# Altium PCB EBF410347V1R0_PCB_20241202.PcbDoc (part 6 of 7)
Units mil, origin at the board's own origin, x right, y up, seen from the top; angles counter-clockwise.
Board outline 5098.43 x 3464.57 mil, 6 copper layers (TOP, GND02, ART03, ART04, PWR05, BOTTOM), stack 47.2 mil thick; 566 components, 452 nets, 1905 pads, 1432 vias.
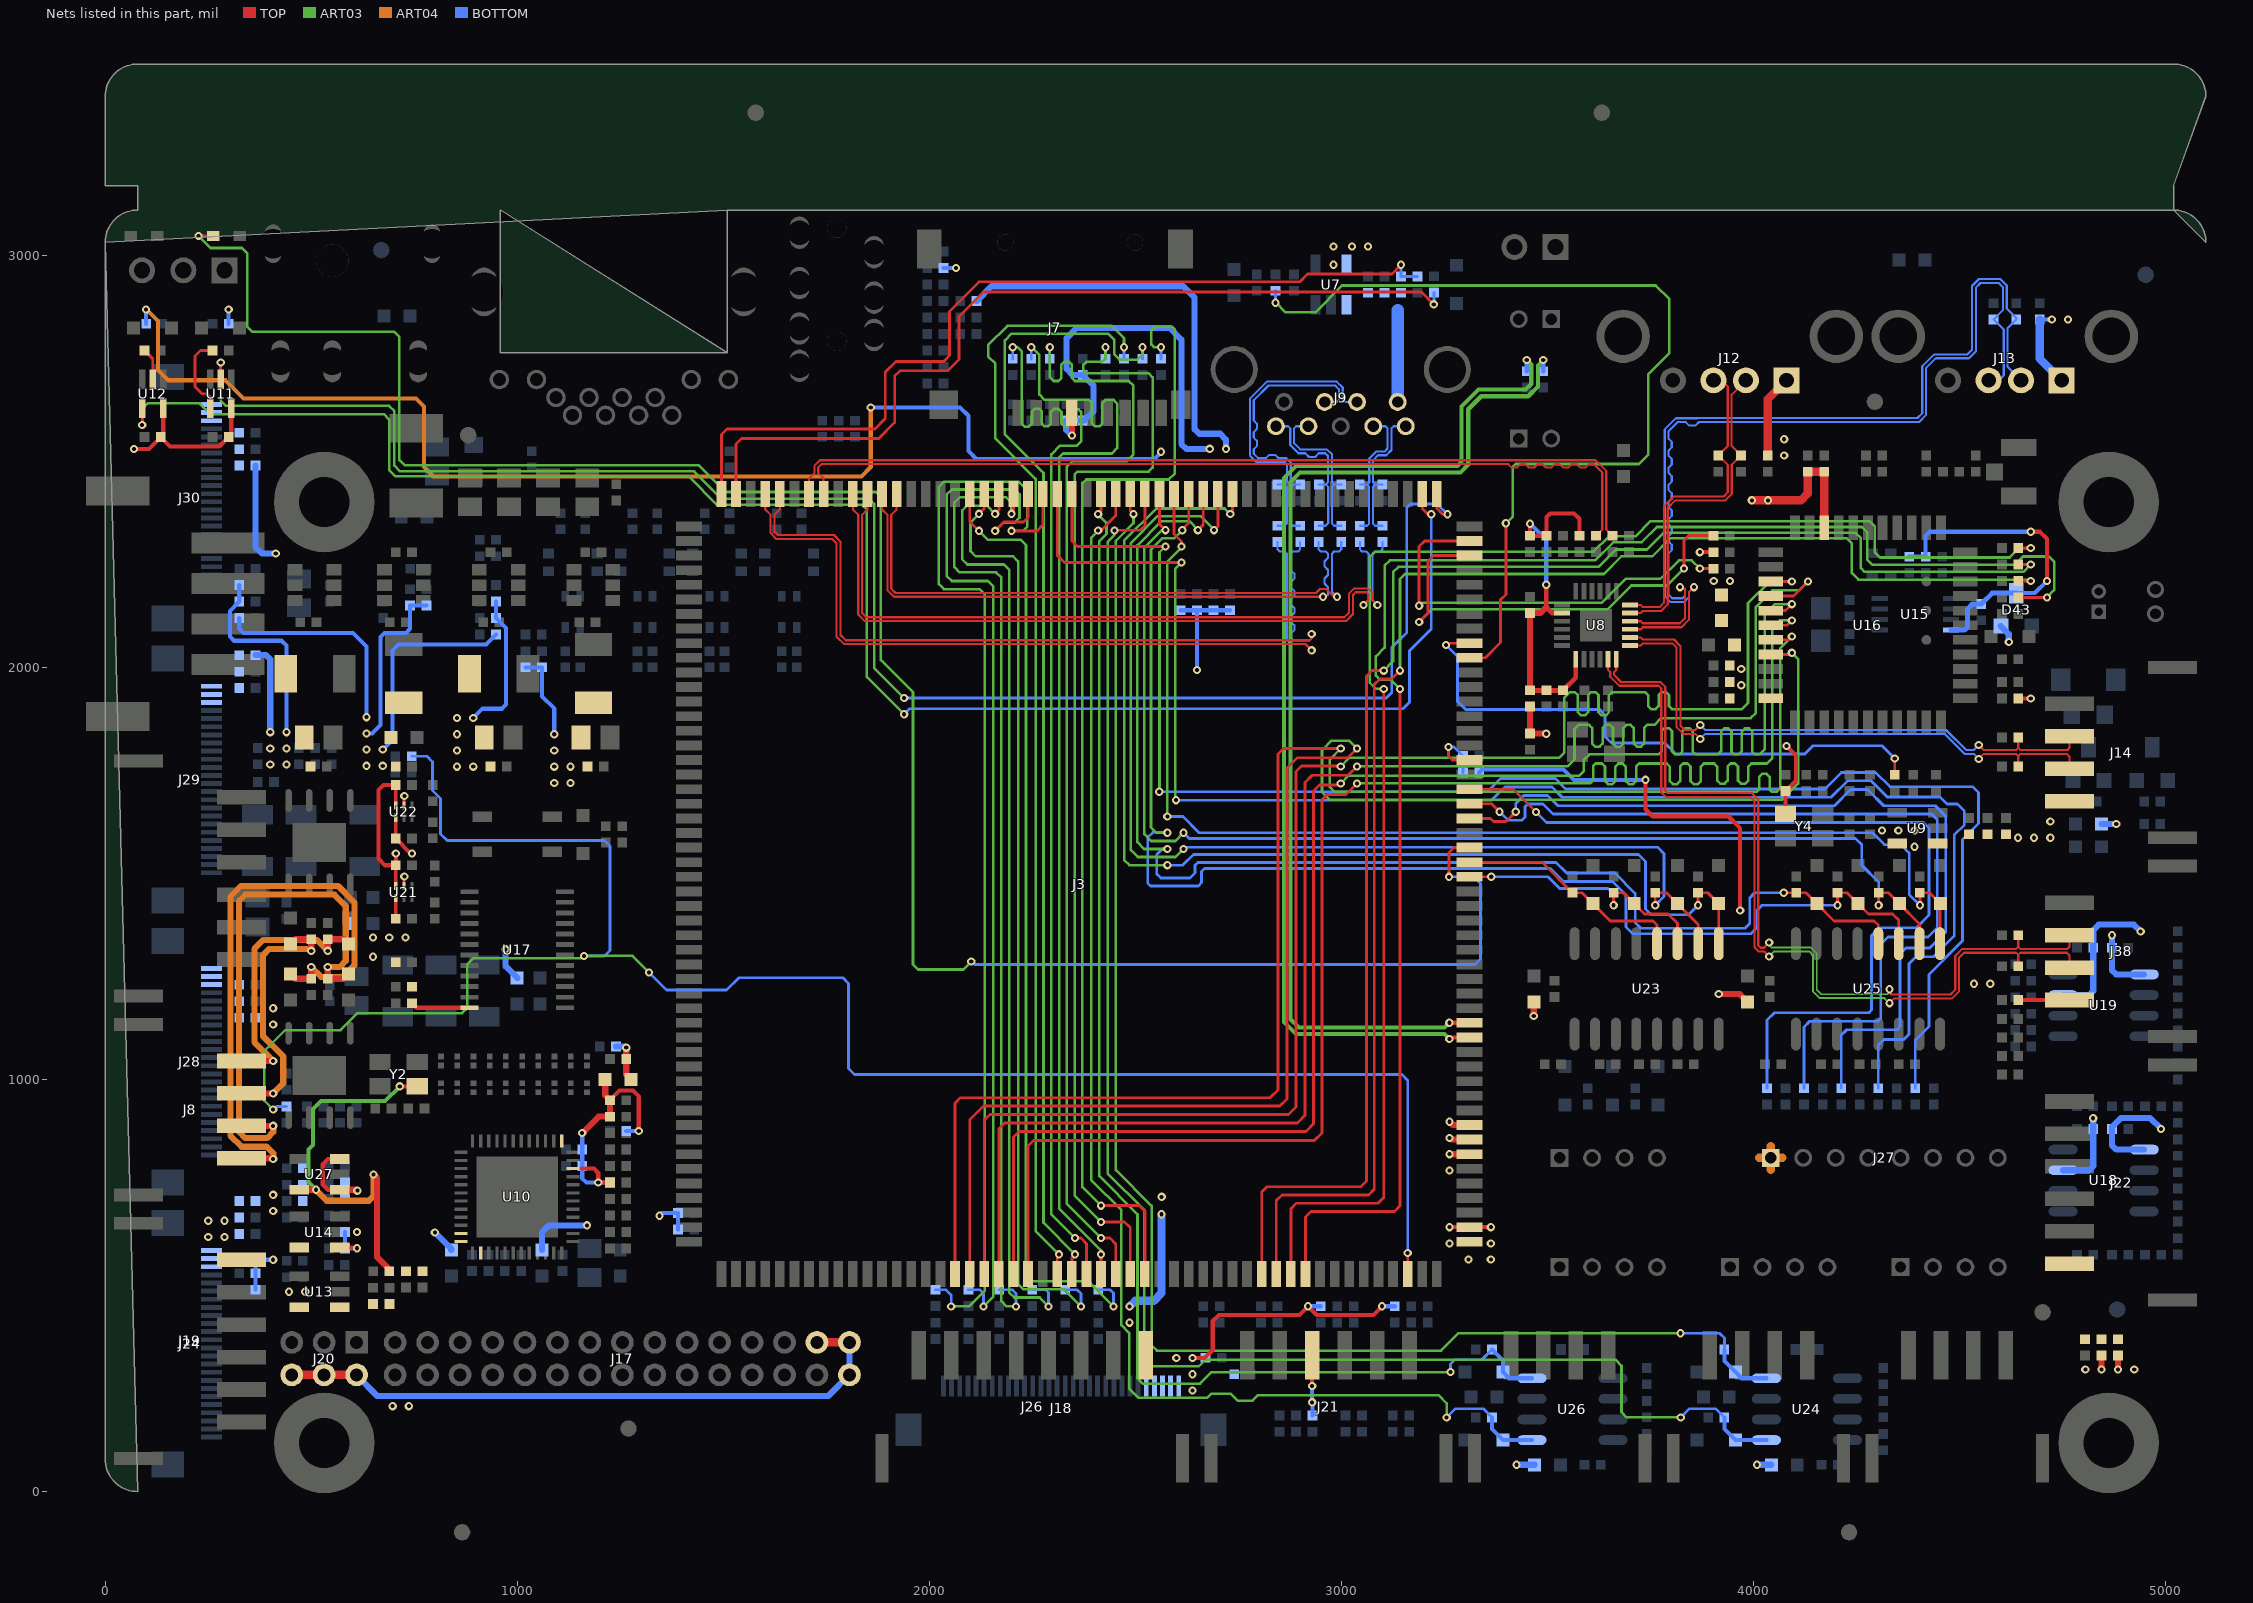
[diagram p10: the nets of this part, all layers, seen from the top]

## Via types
v1: diameter 20, hole 10, TOP to BOTTOM, 1432 vias

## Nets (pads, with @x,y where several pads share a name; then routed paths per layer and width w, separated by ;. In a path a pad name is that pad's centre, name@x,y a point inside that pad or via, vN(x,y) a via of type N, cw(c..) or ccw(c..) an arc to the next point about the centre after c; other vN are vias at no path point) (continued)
SARADC0_IN3: J3.34 R171.2 R173.1 | length 161
  TOP w6.8: v1(3260,1807.05) 3260,1785 3269.45,1775.55 J3.34@3310.59,1775.55
  BOTTOM w6.8: v1(3260,1807.05) 3273.27,1807.05 R173.1@3295.32,1785 R171.2@3295.32,1745
SARADC0_IN5: J3.32 R145.2 | length 2135.4
  TOP w6.8: J3.32@3310.59,1704.68 3416.99,1704.68 v1(3472.26,1649.41)
  BOTTOM w6.8: v1(3472.26,1649.41) 3497.9,1623.77 4412.51,1623.77 4426.11,1610.17 4426.11,1399 4395.34,1368.23 4306.23,1368.23 4287,1349 4287,1168.8 4280.2,1162 4051,1162 4033.11,1144.11 R145.2@4033.11,978.68
SARADC0_IN6: J3.31 R146.2 | length 2139
  TOP w6.8: J3.31@3310.59,1669.25 3364.62,1669.25 v1(3383.99,1649.88)
  BOTTOM w6.8: v1(3383.99,1649.88) 3404.39,1629.48 3438.79,1629.48 3446.11,1636.8 3446.11,1662.2 3452.91,1669 3489.11,1669 3513.94,1644.17 4432.91,1644.17 4446.51,1630.57 4446.51,1369 4423.51,1346 4327,1346 4309,1328 4309,1148.4 4302.2,1141.6 4136.71,1141.6 4123,1127.89 4123,978.79 R146.2@4123.11,978.68
SARADC0_IN7: J3.30 R147.2 | length 2122.7
  TOP w6.8: J3.30@3310.59,1633.82 3362.18,1633.82 3370,1626 3399.48,1626 v1(3423.36,1649.88)
  BOTTOM w6.8: v1(3423.36,1649.88) 3423.36,1670.25 3442.71,1689.6 3500.4,1689.6 3525.43,1664.57 4196.57,1664.57 4236,1704 4277,1704 4316.43,1664.57 4441.36,1664.57 4466.91,1639.02 4466.91,1622.12 4466.91,1357.91 4428,1319 4370,1319 4356,1305 4356,1127.8 4349.2,1121 4226.71,1121 4213.11,1107.4 R147.2@4213.11,978.68
SARADC1_IN0: J3.83 R139.2 | length 2317.3
  TOP w6.8: J3.83@2097.99,2421.22 2097.99,2354.19 v1(2120.55,2331.63)
  ART03 w6.3: v1(2120.55,2331.63) 2141.77,2310.41 2221.59,2310.41 2234.65,2297.35 2234.65,522.6 2247.25,510 2386.22,510 v1(2446.85,449.37)
  BOTTOM w6.8: R139.2@2410,489.68 2439.32,489.68 2446.85,482.15 v1(2446.85,449.37)
SARADC1_IN1: J3.82 R140.2 | length 2280.4
  TOP w6.8: v1(2120.55,2373) 2133.43,2385.87 J3.82@2133.43,2421.22
  ART03 w6.3: v1(2120.55,2373) 2100,2352.45 2100,2282.6 2112.6,2270 2203.15,2270 2215.75,2257.4 2215.75,503.6 2228.35,491 2326.48,491 v1(2368.11,449.37)
  BOTTOM w6.8: R140.2@2330,489.68 2359,489.68 2368.11,480.57 v1(2368.11,449.37)
SARADC1_IN2: J3.81 R141.2 | length 2327.2
  TOP w6.8: v1(2159.92,2373) 2168.86,2381.94 J3.81@2168.86,2421.22
  ART03 w6.3: v1(2159.92,2373) 2139.92,2393 2092,2393 2080,2381 2080,2262.6 2092.6,2250 2181.4,2250 2194,2237.4 2194,483.6 2206.6,471 2267.74,471 v1(2289.37,449.37)
  BOTTOM w6.8: R141.2@2250,489.68 2283,489.68 2289.37,483.31 v1(2289.37,449.37)
SARADC1_IN3: J3.80 R142.2 | length 2381.2
  TOP w6.8: v1(2199.29,2373) 2204.29,2378 J3.80@2204.29,2421.22
  ART03 w6.3: v1(2199.29,2373) 2199.29,2400.6 2186.69,2413.2 2073.6,2413.2 2061,2400.6 2061,2243.5 2073.6,2230.9 2162.4,2230.9 2175,2218.3 2175,461.97 2187.6,449.37 v1(2210.63,449.37)
  BOTTOM w6.8: R142.2@2170,489.68 2202,489.68 2210.63,481.05 v1(2210.63,449.37)
SARADC1_IN4: J3.79 R143.2 | length 2616.3
  TOP w6.8: v1(2159.92,2331.63) 2181.32,2353.03 2229.03,2353.03 2239.72,2363.72 J3.79@2239.72,2421.22
  ART03 w6.3: v1(2131.89,449.37) 2155,472.48 2155,2197.4 2142.4,2210 2054.7,2210 2042.1,2222.6 2042.1,2419.5 2054.7,2432.1 2206.9,2432.1 2219,2420 2219,2363.6 2206.4,2351 2179.29,2351 v1(2159.92,2331.63)
  BOTTOM w6.8: R143.2@2095,489.68 2123,489.68 2131.89,480.79 v1(2131.89,449.37)
SARADC1_IN5: J3.78 R144.2 | length 2733.2
  TOP w6.8: v1(2199.29,2331.63) 2261.56,2331.63 2275.16,2345.23 J3.78@2275.16,2421.22
  ART03 w6.3: v1(2053.15,449.37) 2096.37,449.37 2135,488 2135,2177.4 2122.4,2190 2035.8,2190 2023.2,2202.6 2023.2,2438.4 2035.8,2451 2216,2451 2237.9,2429.1 2237.9,2341.9 2227.63,2331.63 v1(2199.29,2331.63)
  BOTTOM w6.8: R144.2@2015,489.68 2041,489.68 2053.15,477.53 v1(2053.15,449.37)
SARADC1_IN6: J3.77 R148.2 | length 3838.2
  TOP w6.8: J3.77@2310.59,2421.22 2310.59,2272.41 2328.46,2254.54 v1(2612.38,2254.54)
  ART03 w6.3: v1(2599,1678) 2596.6,1680.4 2596.6,2238.76 v1(2612.38,2254.54)
  BOTTOM w6.8: v1(2599,1678) 3365,1678 3397,1710 3511,1710 3536.03,1684.97 4188.08,1684.97 4228.11,1725 4286,1725 4325,1686 4453,1686 4470.23,1668.77 4495.15,1668.77 4512,1651.92 4512,1618 4487.31,1593.31 4487.31,1348.31 4437,1298 4395,1298 4378,1281 4378,1110 4365,1097 4316.71,1097 4303.11,1083.4 R148.2@4303.11,978.68
SARADC1_IN7: J3.76 R149.2 | length 3778.1
  TOP w6.8: J3.76@2346.02,2421.22 2346.02,2307.51 2359.62,2293.91 v1(2573.01,2293.91)
  ART03 w6.3: v1(2558,1698.4) 2558.8,1699.2 2558.8,2279.7 v1(2573.01,2293.91)
  BOTTOM w6.8: v1(2558,1698.4) 3354.4,1698.4 3386.4,1730.4 3519.45,1730.4 3544.48,1705.37 4173.48,1705.37 4213.51,1745.4 4296.6,1745.4 4331.2,1710.8 4531.86,1710.8 4546.45,1696.21 4546.45,1621.45 4507.71,1582.71 4507.71,1336.71 4426,1255 4426,1129.15 4393.11,1096.26 R149.2@4393.11,978.68
SDMMC0_CLK: J3.179 R46.1 | length 2748.3
  TOP w6.8: v1(2416.89,654.58) 2474.16,654.58 2487.76,640.98 J3.179@2487.76,527.52
  ART03 w6.3: v1(2416.89,654.58) 2352.8,718.67 2352.8,2467.99 2360.18,2475.37 2532,2475.37 2542,2485.37 2542,2704.37 2532,2714.37 2382,2714.37 2374,2722.37 2374,2734.37 2381.46,2741.83 2419.07,2741.83 2427.61,2750.37 v1(2427.61,2777.37)
  BOTTOM w6.8: R46.1@2427.61,2749.05 v1(2427.61,2777.37)
SDMMC0_CMD: J3.178 R45.1 | length 2750.7
  TOP w6.8: v1(2416.89,615.21) 2438.72,615.21 2452.32,601.61 J3.178@2452.32,527.52
  ART03 w6.3: v1(2292.61,2777.37) 2292.61,2704.76 2302,2695.37 2313.3,2695.37 2320.68,2702.75 2320.68,2735.07 2326.98,2741.37 2339.58,2741.37 2345.88,2735.07 2345.88,2702.75 2353.26,2695.37 2484,2695.37 2495.15,2684.22 2495.15,2516.52 2479.2,2500.57 2347.1,2500.57 2333.9,2487.37 2333.9,698.2 v1(2416.89,615.21)
  BOTTOM w6.8: R45.1@2292.61,2749.05 v1(2292.61,2777.37)
SDMMC0_D0: J3.174 R47.1 | length 2739.9
  TOP w6.8: J3.174@2310.59,527.52 2310.59,571.91 v1(2314.53,575.84)
  ART03 w6.3: v1(2314.53,575.84) 2258.3,632.07 2258.3,2458.07 2160.18,2556.18 2160.18,2737.82 2143,2755 2143,2783 2189.37,2829.37 2443,2829.37 2472.61,2799.76 v1(2472.61,2777.37)
  BOTTOM w6.8: R47.1@2472.61,2749.05 v1(2472.61,2777.37)
SDMMC0_D1: J3.175 R48.1 | length 2778.6
  TOP w6.8: J3.175@2346.02,527.52 2346.02,567.97 v1(2353.9,575.84)
  ART03 w6.3: v1(2353.9,575.84) 2277.2,652.54 2277.2,2472.17 2183.46,2565.91 2183.46,2793.83 2200,2810.37 2433.4,2810.37 2449,2794.77 2449,2759.97 2461.6,2747.37 2505,2747.37 2517.61,2759.98 v1(2517.61,2777.37)
  BOTTOM w6.8: R48.1@2517.61,2749.05 v1(2517.61,2777.37)
SDMMC0_D2: J3.176 R43.1 | length 2743
  TOP w6.8: v1(2353.9,615.21) 2367.86,615.21 2381.46,601.61 J3.176@2381.46,527.52
  ART03 w6.3: v1(2202.61,2777.37) 2214.63,2777.37 2224,2768 2224,2591.75 2231.38,2584.37 2241.82,2584.37 2249.2,2591.75 2249.2,2620.99 2256.58,2628.37 2266.02,2628.37 2273.4,2620.99 2273.4,2591.75 2279.7,2585.45 2288.61,2585.45 2294.91,2591.75 2294.91,2619.99 2302.29,2627.37 2313.59,2627.37 2320.97,2619.99 2320.97,2591.75 2328.35,2584.37 2337.26,2584.37 2343.56,2590.67 2343.56,2619.99 2349.86,2626.29 2362.21,2626.29 2368.51,2619.99 2368.51,2548.88 2358,2538.37 2332.83,2538.37 ; 2332.82,2538.37 2317.18,2538.37 2296.1,2517.3 2296.1,673.01 v1(2353.9,615.21)
  BOTTOM w6.8: R43.1@2202.61,2749.05 v1(2202.61,2777.37)
SDMMC0_D3: J3.177 R44.1 | length 2742.8
  TOP w6.8: J3.177@2416.89,527.52 v1(2416.89,575.84)
  ART03 w6.3: v1(2247.61,2777.37) 2267,2757.98 2267,2662.37 2280,2649.37 2387.41,2649.37 2394.79,2641.99 2394.79,2592.75 2402.17,2585.37 2412.61,2585.37 2419.99,2592.75 2419.99,2641.99 2427.37,2649.37 2447,2649.37 2456,2640.37 2456,2532.37 2443.1,2519.47 2325,2519.47 2315,2509.47 2315,687 2416.89,585.11 v1(2416.89,575.84)
  BOTTOM w6.8: R44.1@2247.61,2749.05 v1(2247.61,2777.37)
SDMMC0_DETN: J3.180 R49.1 | length 2772.1
  TOP w6.8: v1(2416.89,693.95) 2509.59,693.95 2523.19,680.35 J3.180@2523.19,527.52
  ART03 w6.3: v1(2416.89,693.95) 2371.7,739.14 2371.7,2447.07 2381,2456.37 2581,2456.37 2596,2471.37 2596,2820.07 2588.7,2827.37 2549,2827.37 2539,2817.37 2539,2783.67 2545.3,2777.37 v1(2562.61,2777.37)
  BOTTOM w6.8: R49.1@2562.61,2749.05 v1(2562.61,2777.37)
SDMMC1_CLK: J3.172 U16.17 | length 3921
  TOP w6.8: J3.172@2239.72,527.52 2239.72,838.4 2253.32,852 2934.4,852 2953,870.6 2953,1679 2966,1692 3011.37,1692 v1(3038,1718.63) ; U16.17@4041.89,2102.56 4081.56,2102.56 v1(4093.37,2114.37)
  ART03 w6.3: v1(3038,1718.63) 3603.63,1718.63 3611,1726 3611,1760.7 3617.3,1767 3632.44,1767 3639.82,1759.62 3639.82,1724.38 3647.2,1717 3657.64,1717 3665.02,1724.38 3665.02,1759.62 3672.4,1767 3682.84,1767 3690.22,1759.62 3690.22,1724.38 3697.6,1717 3708.04,1717 3715.42,1724.38 3715.42,1759.62 3722.8,1767 3789.69,1767 3797.07,1759.62 3797.07,1724.28 3804.46,1716.9 3814.89,1716.9 3822.28,1724.28 3822.28,1759.62 3829.66,1767 3840.09,1767 3847.47,1759.62 3847.47,1724.28 3854.86,1716.9 3865.29,1716.9 3872.68,1724.28 3872.68,1759.62 3880.06,1767 3904.86,1767 3912.24,1759.62 3912.24,1725.38 3919.62,1718 3930.06,1718 3937.44,1725.38 3937.44,1759.62 3944.82,1767 3955.26,1767 3962.64,1759.62 3962.64,1725.38 3970.02,1718 3980.46,1718 3987.84,1725.38 3987.84,1759.62 3995.22,1767 4033,1767 4046.06,1780.06 4046.06,2096.06 4064.37,2114.37 v1(4093.37,2114.37)
SDMMC1_CMD: J3.171 U16.16 | length 3935.1
  TOP w6.8: J3.171@2204.29,527.52 2204.29,860.4 2217.89,874 2914,874 2932.6,892.6 2932.6,1700.4 2947.2,1715 2995,1715 v1(2998.63,1718.63) ; U16.16@4041.89,2137.99 4077.62,2137.99 v1(4093.37,2153.74)
  ART03 w6.3: v1(2998.63,1718.63) 3017.78,1737.78 3577.78,1737.78 3588,1748 3588,1775 3602,1789 3769.84,1789 3777.22,1796.38 3777.22,1845.62 3784.61,1853 3795.04,1853 3802.42,1845.62 3802.42,1796.38 3809.8,1789 3820.24,1789 3827.62,1796.38 3827.62,1845.62 3835.01,1853 3845.44,1853 3852.82,1845.62 3852.82,1796.38 3860.2,1789 3913.34,1789 3921.72,1797.38 3921.72,1844.62 3929.1,1852 3939.54,1852 3946.92,1844.62 3946.92,1795.38 3953.3,1789 3963.74,1789 3972.12,1797.38 3972.12,1844.62 3979.5,1852 3989.94,1852 3997.32,1844.62 3997.32,1795.38 4003.7,1789 4015,1789 4027.16,1801.16 4027.16,2128.16 4052.74,2153.74 v1(4093.37,2153.74)
SDMMC1_D0: J3.167 U16.18 | length 3897.6
  TOP w6.8: J3.167@2062.56,527.52 2062.56,942.4 2076.16,956 2827.4,956 2846,974.6 2846,1789.77 2859.6,1803.37 v1(2998.63,1803.37) ; U16.18@4041.89,2067.13 4085.5,2067.13 v1(4093.37,2075)
  ART03 w6.3: v1(2998.63,1803.37) 2972,1776.74 2972,1710 2984,1698 4007.74,1698 4014.12,1704.38 4014.12,1734.62 4021.5,1742 4031.94,1742 4039.32,1734.62 4039.32,1704.38 4045.7,1698 4056,1698 4064.96,1706.96 4064.96,2046.59 v1(4093.37,2075)
SDMMC1_D1: J3.168 U16.19 | length 3918.1
  TOP w6.8: J3.168@2097.99,527.52 2097.99,901.99 2131.6,935.6 2850.6,935.6 2868,953 2868,1756 2893.2,1781.2 3015.83,1781.2 v1(3038,1803.37) ; U16.19@4041.89,2031.69 4089.43,2031.69 v1(4093.37,2035.63)
  ART03 w6.3: v1(3038,1803.37) 3018.85,1822.52 2976.52,1822.52 2953.1,1799.1 2953.1,1697.9 2972,1679 4069,1679 4108.52,1718.52 4108.52,2020.48 v1(4093.37,2035.63)
SDMMC1_D2: J3.169 U16.14 | length 3928.4
  TOP w6.8: J3.169@2133.43,527.52 2133.43,901.6 2147.03,915.2 2871.4,915.2 2890,933.8 2890,1747.2 2903.6,1760.8 2997.83,1760.8 v1(2998.63,1760) ; U16.14@4041.89,2208.86 v1(4093.37,2208.86)
  ART03 w6.3: v1(2998.63,1760) 3019.63,1781 3529,1781 3541,1793 3541,1926 3555.15,1940.15 3566.45,1940.15 3573.83,1932.77 3573.83,1891.38 3581.21,1884 3591.65,1884 3599.03,1891.38 3599.03,1932.77 3606.41,1940.15 3616.85,1940.15 3624.23,1932.77 3624.23,1891.38 3631.61,1884 3642.05,1884 3649.43,1891.38 3649.43,1932.77 3656.81,1940.15 3737.38,1940.15 3744.76,1932.77 3744.76,1906.38 3752.14,1899 3762.58,1899 3769.96,1906.38 3769.96,1932.77 3777.34,1940.15 3787.78,1940.15 3795.16,1932.77 3795.16,1906.38 3802.54,1899 3972,1899 3987,1914 3987,2156 4039.86,2208.86 v1(4093.37,2208.86)
SDMMC1_D3: J3.170 U16.15 | length 3906.8
  TOP w6.8: J3.170@2168.86,527.52 2168.86,881.2 2182.46,894.8 2893.6,894.8 2912.2,913.39 2912.2,1721.19 2929.4,1738.4 3016.4,1738.4 v1(3038,1760) ; U16.15@4041.89,2173.43 4097.31,2173.43 v1(4132.74,2208.86)
  ART03 w6.3: v1(3038,1760) 3549,1760 3566,1777 3566,1851 3576,1861 3601.47,1861 3608.85,1853.62 3608.85,1815.28 3616.23,1807.9 3626.67,1807.9 3634.05,1815.28 3634.05,1853.62 3641.43,1861 3651.87,1861 3659.25,1853.62 3659.25,1815.28 3666.63,1807.9 3677.07,1807.9 3684.45,1815.28 3684.45,1853.62 3691.83,1861 3702.27,1861 3709.65,1853.62 3709.65,1815.28 3717.03,1807.9 3727.47,1807.9 3734.85,1815.28 3734.85,1853.62 3742.23,1861 3760,1861 3776,1877 3993,1877 4005.9,1889.9 4005.9,2146.9 4046,2187 4110.88,2187 v1(4132.74,2208.86)
SPK_CTRL: J3.198 R25.1 R39.1 | length 4845.2
  TOP w6.8: J3.198@3160.98,527.52 v1(3160.98,578.98)
  ART03 w6.3: v1(407.72,927.01) 386,948.73 386,1069 437,1120 571,1120 612,1161 866.4,1161 879,1173.6 879,1280 893,1294 1156,1294 v1(1162,1300) 1279.63,1300 v1(1320,1259.63)
  BOTTOM w6.8: v1(407.72,927.01) 415.39,934.68 R25.1@440,934.68 ; R39.1@744,1784.68 780.8,1784.68 794.4,1771.08 794.4,1701.6 814,1682 814,1596 830,1580 1211.4,1580 1225,1566.4 1225,1313.6 1211.4,1300 v1(1162,1300) ; v1(1320,1259.63) 1362.63,1217 1508,1217 1538,1247 1790.4,1247 1804,1233.4 1804,1026.6 1818.6,1012 3147.38,1012 3160.98,998.4 v1(3160.98,578.98)
SPK_LN: C38.1 J8.2 L6.2 | length 1291
  TOP w15: J8.2@330.71,887.64 v1(407.72,887.64) ; v1(540,1273) C38.1@540,1244.68 578.18,1244.68 L6.2@590,1256.5
  ART04 w15: v1(407.72,887.64) 407.72,873 392.72,858 340,858 325,873 325,1434 340,1449 556,1449 584,1421 584,1288 569,1273 v1(540,1273)
SPK_LP: C37.1 J8.1 L7.2 | length 1484.6
  TOP w15: J8.1@330.71,808.9 405.72,808.9 v1(407.72,806.9) ; L7.2@450,1256.5 461.82,1244.68 C37.1@500,1244.68 v1(500,1273)
  ART04 w15: v1(407.72,806.9) 407.72,821 391.72,837 331,837 304,864 304,1444 330,1470 565,1470 605,1430 605,1277 577,1249 524,1249 v1(500,1273)
SPK_RN: C49.1 J8.3 L8.2 | length 651
  TOP w15: J8.3@330.71,966.38 v1(407.72,966.38) ; L8.2@450,1328.5 461.82,1340.32 C49.1@500,1340.32 v1(500,1312.37)
  ART04 w15: v1(407.72,966.38) 432,990.66 432,1056 383,1105 383,1302 398,1317 495.37,1317 v1(500,1312.37)
SPK_RP: C48.1 J8.4 L9.2 | length 648.8
  TOP w15: J8.4@330.71,1045.12 v1(407.72,1045.12) ; v1(540,1312.37) C48.1@540,1340.32 578.18,1340.32 L9.2@590,1328.5
  ART04 w15: v1(407.72,1045.12) 362,1090.84 362,1317 384,1339 513.37,1339 v1(540,1312.37)
SPKN_OUT: J3.16 R42.1 | length 2622.9
  TOP w10: v1(3262.21,1137.76) J3.16@3310.59,1137.76
  ART03 w10: v1(3262.21,1137.76) 3250.78,1126.32 2896.8,1126.32 2876.8,1146.32 2876.8,2450.37 2899.8,2473.37 3289,2473.37 3308,2492.37 3308,2626.74 3339.63,2658.37 3453.63,2658.37 3477,2681.74 3477,2733.37 v1(3490,2746.37)
  BOTTOM w10: R42.1@3490,2719.05 v1(3490,2746.37)
SPKP_OUT: J3.15 R41.1 | length 2652.2
  TOP w10: v1(3262.21,1098.39) 3266.15,1102.32 J3.15@3310.59,1102.32
  ART03 w10: v1(3262.21,1098.39) 3250.28,1110.32 2889.68,1110.32 2860.8,1139.2 2860.8,2459.8 2890.37,2489.37 3282,2489.37 3292,2499.37 3292,2633.37 3333,2674.37 3447,2674.37 3461,2688.37 3461,2735.37 v1(3450,2746.37)
  BOTTOM w10: R41.1@3450,2719.05 v1(3450,2746.37)
SYS_LED: J3.28 LED2.1 | length 5180
  TOP w6.8: v1(226.32,3047.24) LED2.1@262,3047.24 ; v1(3261.11,1492) 3261.11,1551 3273.06,1562.95 J3.28@3310.59,1562.95
  ART03 w6.3: v1(226.32,3047.24) 255.56,3018 332,3018 344.5,3005.5 344.5,2827.1 356.6,2815 701.4,2815 714,2802.4 714,2503.6 726.6,2491 1440,2491 1505,2426 1870.1,2426 1882.7,2413.4 1882.7,2018.3 1960.4,1940.6 1960.4,1279.6 1973,1267 2082.6,1267 v1(2102,1286.4)
  BOTTOM w6.8: v1(2102,1286.4) 2109.4,1279 3324.4,1279 3338,1292.6 3338,1476 3322,1492 v1(3261.11,1492)
UART0_RX: R70.2 U12.2 | length 77.9
  TOP w6.8: R70.2@95.32,2769.37 115.31,2749.37 U12.2@115.31,2699.8
UART0_RX_M0_DEBUG: J3.52 U12.4 | length 4336.5
  TOP w6.8: v1(89.72,2588.65) U12.4@89.72,2628.94 ; J3.52@3196.42,2421.22 3196.42,2385.6 3210.02,2372 v1(3218.11,2372)
  ART03 w6.3: v1(89.72,2588.65) 89.72,2627.72 103,2641 229,2641 255,2615 676.4,2615 689,2602.4 689,2479 704.3,2463.7 1416.3,2463.7 1485.3,2394.7 1837.1,2394.7 1848.59,2383.21 1848.59,1977.04 v1(1939,1886.63)
  BOTTOM w6.8: v1(1939,1886.63) 1952.37,1900 3150,1900 3165.8,1915.8 3165.8,2040.8 3218.11,2093.11 v1(3218.11,2372)
UART0_TX: R69.2 U11.4 | length 197
  TOP w6.8: U11.4@254.72,2628.94 254.72,2656.65 247,2664.37 235,2664.37 218,2681.37 218,2755.77 231.6,2769.37 R69.2@260.32,2769.37
UART0_TX_M0_DEBUG: J3.51 U11.2 | length 4233.4
  TOP w6.8: U11.2@280.31,2699.8 v1(280.31,2740.05) ; J3.51@3231.85,2421.22 3231.85,2386.15 3246,2372 v1(3257.48,2372)
  ART03 w6.3: v1(280.31,2740.05) 280.31,2647.6 292.92,2635 689.1,2635 701.7,2622.4 701.7,2490.28 715.98,2476 1429,2476 1495,2410 1853.38,2410 1865.98,2397.4 1865.98,1999.02 v1(1939,1926)
  BOTTOM w6.8: v1(1939,1926) 3108.91,1926 3122.51,1939.6 3122.51,2048.51 3159,2085 3159,2389 3167,2397 3232.48,2397 v1(3257.48,2372)
UART1_CTSN_M0: J3.191 R150.1 | length 3900.4
  TOP w6.8: J3.191@2912.95,527.52 2912.95,666.4 2926.55,680 3128.88,680 3142.48,693.6 v1(3142.48,1948) ; R150.1@4642.79,2170 v1(4712.48,2170)
  ART03 w6.3: v1(3142.48,1948) 3120.48,1970 3094,1970 3083.96,1980.04 3083.96,2026.96 3105,2048 3105,2247.4 3117.6,2260 3616,2260 3660,2304 3729,2304 3766,2341 4263.4,2341 4276,2328.4 4276,2261.6 4288.6,2249 4634,2249 4654.4,2269.4 4717.4,2269.4 4730,2256.8 4730,2187.52 v1(4712.48,2170)
UART1_RTSN_M0: J3.190 R154.1 | length 3728.9
  TOP w6.8: J3.190@2877.52,527.52 2877.52,686.4 2891.12,700 3089.51,700 3103.11,713.6 v1(3103.11,1948) ; R154.1@4642.79,2290 v1(4673.11,2290)
  ART03 w6.3: v1(3103.11,1948) 3084,1948 3069,1963 3069,2268.4 3081.6,2281 3612,2281 3649.42,2318.42 3713.42,2318.42 3750,2355 4282.4,2355 4295,2342.4 4295,2279.6 4307.6,2267 4622,2267 4644,2289 4672.11,2289 v1(4673.11,2290)
UART1_RX_M0: J3.189 R152.1 | length 3639.1
  TOP w6.8: J3.189@2842.09,527.52 2842.09,706.4 2855.69,720 3066.4,720 3080,733.6 3080,1958.4 3093.6,1972 3122.11,1972 v1(3142.48,1992.37) ; R152.1@4642.79,2210 v1(4673.11,2210)
  ART03 w6.3: v1(3142.48,1992.37) 3142.48,2214.4 3155.08,2227 3637,2227 3680,2270 3755,2270 3799,2314 4226.4,2314 4239,2301.4 4239,2229 4255,2213 4670.11,2213 v1(4673.11,2210)
UART1_TX_M0: J3.188 R153.1 | length 3692.8
  TOP w6.8: J3.188@2806.65,527.52 2806.65,726.4 2820.25,740 3047.4,740 3061,753.6 3061,1978.77 3074.6,1992.37 v1(3103.11,1992.37) ; R153.1@4642.79,2250 v1(4673.11,2250)
  ART03 w6.3: v1(3103.11,1992.37) 3126,2015.26 3126,2231.49 3138.6,2244.09 3624.09,2244.09 3666.3,2286.3 3741.3,2286.3 3782,2327 4248.4,2327 4261,2314.4 4261,2241 4270,2232 4655.11,2232 v1(4673.11,2250)
UART2_RX_M1: D64.1 J3.27 R116.1 U23.12 | length 564.1
  TOP w6.8: J3.27@3310.59,1527.52 3486.71,1527.52 R116.1@3560.91,1453.32 3584.33,1453.32 D64.1@3610.91,1426.74 3652.65,1385 3756.31,1385 3766.31,1375 U23.12@3766.31,1329.8
UART2_TX_M1: D65.1 J3.26 R118.1 U23.11 | length 660.2
  TOP w6.8: J3.26@3310.59,1492.09 v1(3364,1492.09) ; v1(3660.91,1423) R118.1@3660.91,1453.32 3684.33,1453.32 D65.1@3710.91,1426.74 3735.65,1402 3793.11,1402 3815.91,1379.2 U23.11@3815.91,1329.8
  BOTTOM w6.8: v1(3364,1492.09) 3501.91,1492.09 3530,1464 3647,1464 3660.91,1450.09 v1(3660.91,1423)
UART3_RX_M1: D62.1 J3.65 R113.1 U23.9 | length 2855.8
  TOP w6.8: v1(2730.49,2372.65) 2735.79,2377.95 J3.65@2735.79,2421.22 ; v1(3865.91,1423) R113.1@3865.91,1453.32 3889.33,1453.32 D62.1@3915.91,1426.74 U23.9@3915.91,1329.8
  ART03 w6.3: v1(2577.7,1520.26) 2485.6,1520.26 2473,1532.86 2473,2308 2551,2386 2717,2386 2730.35,2372.65 v1(2730.49,2372.65)
  BOTTOM w6.8: v1(2577.7,1520.26) 2615.26,1520.26 2641,1546 3721,1546 3738.11,1528.89 3738.11,1413.6 3751.71,1400 3842.91,1400 v1(3865.91,1423)
UART3_TX_M1: D63.1 J3.66 R114.1 U23.10 | length 2745.5
  TOP w6.8: v1(2691.12,2333.28) 2700.35,2342.51 J3.66@2700.35,2421.22 ; v1(3761.91,1423) R114.1@3761.91,1453.32 3789.33,1453.32 D63.1@3815.91,1426.74 3866.31,1376.34 U23.10@3866.31,1329.8
  ART03 w6.3: v1(2617.07,1559.63) 2597.44,1540 2506,1540 2489,1557 2489,2302 2554.3,2367.3 2658.7,2367.3 2668.3,2357.7 2691.12,2334.88 v1(2691.12,2333.28)
  BOTTOM w6.8: v1(2617.07,1559.63) 2621.44,1564 3767,1564 3783,1548 3783,1444.09 v1(3761.91,1423)
UART4_RX_M0: D71.1 J3.67 R126.1 U25.12 | length 3191.6
  TOP w6.8: v1(2651.75,2333.28) 2664.92,2346.45 J3.67@2664.92,2421.22 ; v1(4073.79,1453.32) R126.1@4104.11,1453.32 4127.53,1453.32 D71.1@4154.11,1426.74 4195.85,1385 4293.11,1385 4303.31,1374.8 U25.12@4303.31,1329.8
  ART03 w6.3: v1(2577.7,1559.63) 2521.6,1559.63 2505,1576.23 2505,2296 2564,2355 2631,2355 2651.75,2334.25 v1(2651.75,2333.28)
  BOTTOM w6.8: v1(2577.7,1559.63) 2565.6,1559.63 2552,1546.03 2552,1499 2562,1489 2633,1489 2645,1501 2645,1520.2 2651.8,1527 3521,1527 3547,1501 3664,1501 3713.11,1451.89 3713.11,1380.83 3726.71,1367.23 3979.34,1367.23 3991.11,1379 3991.11,1441 4003.43,1453.32 v1(4073.79,1453.32)
UART4_TX_M0: D72.1 J3.68 R128.1 U25.11 | length 3211.2
  TOP w6.8: v1(2614,2333) 2614,2334.9 2629.49,2350.39 J3.68@2629.49,2421.22 ; v1(4204.11,1423) R128.1@4204.11,1453.32 4227.53,1453.32 D72.1@4254.11,1426.74 4279.26,1401.59 4338.11,1401.59 4352.91,1386.79 U25.11@4352.91,1329.8
  ART03 w6.3: v1(2577.7,1599) 2550.6,1599 2538,1611.6 2538,2286 2565.85,2313.85 2594.85,2313.85 v1(2614,2333)
  BOTTOM w6.8: v1(2577.7,1599) 2576.7,1600 2543,1600 2530,1587 2530,1477 2537,1470 2653,1470 2661,1478 2661,1505.2 2667.8,1512 3508,1512 3539,1481 3658,1481 3691.11,1447.89 3691.11,1370 3707.11,1354 3994.11,1354 4009.11,1369 4009.11,1411 4021.11,1423 v1(4204.11,1423)
UART7_RX_M0: D69.1 J3.69 R123.1 U25.9 | length 2968.4
  TOP w6.8: J3.69@2594.05,2421.22 2594.05,2323.95 2612.38,2305.62 v1(2612.38,2293.91) ; v1(4404.11,1423) R123.1@4404.11,1453.32 4427.53,1453.32 D69.1@4454.11,1426.74 4452.91,1425.54 U25.9@4452.91,1329.8
  ART03 w6.3: v1(2577.7,1638.37) 2577.7,2256.7 2612.38,2291.38 v1(2612.38,2293.91)
  BOTTOM w6.8: v1(2577.7,1638.37) 2615.63,1638.37 2655,1599 4289.11,1599 4318.11,1570 4358.11,1570 4378.11,1550 4378.11,1449 v1(4404.11,1423)
UART7_TX_M0: D70.1 J3.70 R124.1 U25.10 | length 2998.7
  TOP w6.8: J3.70@2558.62,2421.22 2558.62,2347.66 v1(2573.01,2333.28) ; v1(4304.11,1423) R124.1@4304.11,1453.32 4327.53,1453.32 D70.1@4354.11,1426.74 4403.31,1377.54 U25.10@4403.31,1329.8
  ART03 w6.3: v1(2573.01,2333.28) 2564.28,2333.28 2522,2291 2522,1595.6 2538.6,1579 2597.07,1579 v1(2617.07,1599)
  BOTTOM w6.8: v1(2617.07,1599) 2631.07,1585 4248.11,1585 4263.11,1570 4263.11,1520 4304.11,1479 v1(4304.11,1423)
UART8_RX_M0: D60.1 J3.71 R115.1 U24.1 | length 3917
  TOP w6.8: v1(2449.26,2332.74) 2449.52,2333 2512,2333 2523.19,2344.19 J3.71@2523.19,2421.22
  ART03 w6.3: v1(2449.26,2332.74) 2449.26,2321.26 2432.85,2304.85 2432.85,772.15 2521.88,683.12 2521.88,318.12 2536,304 2654,304 2670,320 3665,320 3680,305 3680,192.6 3692.6,180 v1(3823.63,180)
  BOTTOM w6.8: v1(3823.63,180) 3844.83,201.2 3908.48,201.2 R115.1@3929.68,180
  BOTTOM w10: R115.1@3929.68,180 3929.68,151.58 D60.1@3956.26,125 U24.1@4031.57,125
UART8_TX_M0: D61.1 J3.72 R117.1 U24.4 | length 3716.1
  TOP w6.8: J3.72@2487.76,2421.22 2487.76,2379.98 v1(2495.63,2372.11)
  ART03 w6.3: v1(2495.63,2372.11) 2495.63,2350.23 2453,2307.6 2453,780 2539.66,693.34 2539.66,354.6 2552.26,342 3242,342 3284.37,384.37 v1(3823,384.37)
  BOTTOM w6.8: v1(3823,384.37) 3917.63,384.37 3929.68,372.32 R117.1@3929.68,345
  BOTTOM w10: R117.1@3929.68,345 3929.68,316.58 D61.1@3956.26,290 3971.26,275 U24.4@4031.57,275
UART9_RX_M1: D67.1 J3.73 R125.1 U26.1 | length 3339.9
  TOP w6.8: v1(2409.89,2332.74) 2416.89,2332.74 2452.32,2368.17 J3.73@2452.32,2421.22
  ART03 w6.3: v1(2409.89,2332.74) 2409.89,2331.74 2393.48,2315.33 2393.48,755.52 2466,683 2466,404 2485,385 2485,250 2507,228 2675,228 2684,237 2732,237 2748.5,220.5 2784.5,220.5 2798,234 3236,234 3255.63,214.37 v1(3255.63,180)
  BOTTOM w6.8: v1(3255.63,180) 3276.83,201.2 3344.48,201.2 R125.1@3365.68,180
  BOTTOM w10: R125.1@3365.68,180 3365.68,151.58 D67.1@3392.26,125 U26.1@3462.57,125
UART9_TX_M1: D68.1 J3.74 R127.1 U26.4 | length 3257.6
  TOP w6.8: v1(2409.89,2372.11) 2416.89,2379.11 J3.74@2416.89,2421.22
  ART03 w6.3: v1(2409.89,2372.11) 2409.89,2371.11 2430,2351 2430,2324 2412.63,2306.63 2412.63,765.37 2505.37,672.63 2505.37,274.6 2517.97,262 2657,262 2685,290 v1(3265,290)
  BOTTOM w6.8: v1(3265,290) 3265,310 3275,320 3340.68,320 R127.1@3365.68,345
  BOTTOM w10: R127.1@3365.68,345 3392.26,318.42 D68.1@3392.26,290 3407.26,275 U26.4@3462.57,275
USB20_HOST1_DM: J3.94 R65.2 | length 2175.4
  TOP w5.2: J3.94@1708.23,2421.22 1708.23,2458.79 1721.24,2471.8 1721.24,2489.54 1734.71,2503 3617,2503 3642.81,2477.19 3642.81,2334.98 R65.2@3658.11,2319.68
USB20_HOST1_DP: J3.93 R64.2 | length 2179.9
  TOP w5.2: J3.93@1743.66,2421.22 1743.66,2458.79 1730.64,2471.8 1730.64,2485.64 1738.6,2493.6 3405.1,2493.6 3413.7,2485 3425.9,2485 3434.5,2493.6 3446.7,2493.6 3455.3,2485 3467.5,2485 3476.1,2493.6 3488.3,2493.6 3496.9,2485 3509.1,2485 3517.7,2493.6 3529.9,2493.6 3538.5,2485 3550.7,2485 3559.3,2493.6 3571.5,2493.6 3580.1,2485 3592.3,2485 3600.9,2493.6 3613.11,2493.6 3633.41,2473.3 3633.41,2334.98 R64.2@3618.11,2319.68
USB20_HUB_PWR_EN: J3.42 R67.1 | length 1412.1
  TOP w6.8: v1(3254,2054.63) 3258.39,2059.02 J3.42@3310.59,2059.02 ; R67.1@4343.11,1739.68 v1(4343.11,1779.45)
  BOTTOM w6.8: v1(3254,2054.63) 3282,2026.63 3282,1918 3302.12,1897.88 3627.12,1897.88 3640,1885 3640,1833 3656,1817 3785,1817 3812.15,1789.85 4124.85,1789.85 4145,1810 4312.56,1810 v1(4343.11,1779.45)
USB30_DM: D17.1 J9.2 R52.1 | length 741.9
  BOTTOM w5.2: R52.1@2845,2344.05 2862.4,2344.05 2867.6,2349.25 2867.6,2437.37 2860.92,2444.05 ; D17.1@2845,2444.05 2860.92,2444.05 ; J9.2@3038.22,2644.5 3008.75,2644.5 3003.55,2649.7 3003.55,2679.45 2989.23,2693.77 2819.4,2693.77 2778,2652.37 2778,2514.71 2794.23,2498.48 2862.6,2498.48 2867.8,2493.28 2867.8,2450.93 2860.92,2444.05
USB30_DP: D18.1 J9.3 R53.1 | length 730.7
  BOTTOM w5.2: R53.1@2900,2344.05 2882.2,2344.05 2877,2349.25 2877,2437.37 2883.68,2444.05 ; D18.1@2900,2444.05 2883.68,2444.05 ; J9.3@2959.48,2644.5 2988.95,2644.5 2994.15,2649.7 2994.15,2675.56 2985.34,2684.37 2823.29,2684.37 2787.4,2648.48 2787.4,2599.56 2795,2591.96 2795,2578.76 2787.4,2571.16 2787.4,2557.96 2795,2550.36 2795,2537.16 2787.4,2529.56 2787.4,2518.6 2798.12,2507.88 2816.58,2507.88 2824.7,2516 2839.38,2516 2847.5,2507.88 2866.49,2507.88 2877.2,2497.17 2877.2,2450.53 2883.68,2444.05
USB30_OTG0_DM: J3.97 R52.2 | length 1988.8
  TOP w5.2: J3.97@1601.93,2421.22 1601.93,2383.64 1614.95,2370.63 1614.95,2326.05 1629,2312 1764.71,2312 1775,2301.71 1775,2075 1793.39,2056.61 2913.01,2056.61 v1(2928,2041.63)
  BOTTOM w5.2: R52.2@2845,2304.69 2845,2286.81 2850.2,2281.61 2862.6,2281.61 2867.8,2276.41 2867.8,2067.91 2879.09,2056.61 2913.01,2056.61 v1(2928,2041.63)
USB30_OTG0_DP: J3.96 R53.2 | length 1998.3
  TOP w5.2: J3.96@1637.36,2421.22 1637.36,2383.64 1624.35,2370.63 1624.35,2329.95 1632.89,2321.4 1768.6,2321.4 1784.4,2305.6 1784.4,2078.89 1797.28,2066.01 2922.8,2066.01 2928,2071.22 v1(2928,2081)
  BOTTOM w5.2: R53.2@2900,2304.69 2900,2286.81 2894.8,2281.61 2882.4,2281.61 2877.2,2276.41 2877.2,2236.4 2886,2227.6 2886,2215.6 2877.2,2206.8 2877.2,2194.8 2886,2186 2886,2174 2877.2,2165.2 2877.2,2153.2 2886,2144.4 2886,2132.4 2877.2,2123.6 2877.2,2111.6 2886,2102.8 2886,2090.8 2877.2,2082 2877.2,2071.8 2882.99,2066.01 2922.8,2066.01 2928,2071.22 v1(2928,2081)
USB30_OTG0_ID: J3.99 R193.2 | length 2136.5
  TOP w6.8: J3.99@1531.06,2421.22 1531.06,2542.4 1544.66,2556 1877.53,2556 1916,2594.47 1916,2707.47 1928.53,2720 2044.53,2720 2072,2747.47 2072,2852 2131.54,2911.54 3194.2,2911.54 v1(3224.37,2881.37)
  BOTTOM w6.8: v1(3224.37,2881.37) 3225,2882 R193.2@3225,2910.32
USB30_OTG0_SSRXN: J3.89 R54.2 | length 1476.4
  TOP w5.2: J3.89@1885.39,2421.22 1885.39,2383.64 1898.41,2370.63 1898.41,2187.51 1914.32,2171.6 v1(2955.57,2171.6)
  BOTTOM w5.2: R54.2@2945,2304.69 2945,2286.81 2950.2,2281.61 2962.6,2281.61 2967.8,2276.41 2967.8,2266.21 2959,2257.41 2959,2245.41 2967.8,2236.61 2967.8,2224.61 2959,2215.81 2959,2203.81 2967.8,2195.01 2967.8,2176.8 2962.6,2171.6 v1(2955.57,2171.6)
USB30_OTG0_SSRXP: J3.88 R55.2 | length 1487.8
  TOP w5.2: J3.88@1920.83,2421.22 1920.83,2383.64 1907.81,2370.63 1907.81,2191.4 1918.21,2181 2938.66,2181 2948.26,2190.6 2963.4,2190.6 2982.4,2171.6 v1(2989.43,2171.6)
  BOTTOM w5.2: v1(2989.43,2171.6) 2977.2,2183.83 2977.2,2276.41 2982.4,2281.61 2994.8,2281.61 3000,2286.81 R55.2@3000,2304.69
USB30_OTG0_SSTXN: C63.2 J3.91 | length 1805.7
  TOP w5.2: J3.91@1814.53,2421.22 1814.53,2383.64 1827.54,2370.63 1827.54,2128.51 1843.45,2112.6 3011.29,2112.6 3028.4,2129.71 3028.4,2176.11 3034.89,2182.6 3060.6,2182.6 3065.8,2177.4 3065.8,2163.83 v1(3053.57,2151.6)
  BOTTOM w5.2: C63.2@3045,2304.69 3045,2286.81 3050.2,2281.61 3060.6,2281.61 3066.6,2275.61 3066.6,2164.63 v1(3053.57,2151.6)
USB30_OTG0_SSTXP: C64.2 J3.90 | length 1806.7
  TOP w5.2: J3.90@1849.96,2421.22 1849.96,2383.64 1836.94,2370.63 1836.94,2132.4 1847.34,2122 3007.4,2122 3019,2133.6 3019,2180 3031,2192 3064.49,2192 3075.2,2181.29 3075.2,2163.83 v1(3087.43,2151.6)
  BOTTOM w5.2: v1(3087.43,2151.6) 3076,2163.03 3076,2274.41 3083.2,2281.61 3094.8,2281.61 3100,2286.81 C64.2@3100,2304.69
USB30_OTG0_VBUSDET: J3.100 R58.2 R59.1 | length 2161.4
  TOP w6.8: J3.100@1495.63,2421.22 1495.63,2565.4 1509.23,2579 1868,2579 1893,2604 1893,2717 1919,2743 2035,2743 2049,2757 2049,2864 2121,2936 2899,2936 2918,2955 3122.63,2955 v1(3145,2977.37)
  BOTTOM w6.8: v1(3145,2977.37) R58.2@3145,2949.05 R59.1@3185,2949.05
USB30_OTG_PWR_EN: J3.41 R56.1 | length 2305.3
  TOP w6.8: J3.41@3310.59,2023.58 3349.58,2023.58 3386.57,2060.57 3386.57,2164.57 3399.34,2177.34 v1(3399.34,2350)
  ART03 w6.3: v1(2840,2885.37) 2841.37,2885.37 2864.74,2862 2937,2862 3002,2927 3763,2927 3796,2894 3796,2763 3745,2712 3745,2517 3722,2494 3422.64,2494 3416.34,2487.7 3416.34,2367 v1(3399.34,2350)
  BOTTOM w6.8: v1(2840,2885.37) R56.1@2840,2914.69
USB30_OTG_VBUS: C66.1 C67.1 J9.1 R58.1 U7.1 | length 222.5
  BOTTOM w30: J9.1@3136.64,2644.5 3136.64,2867.01
USB30_RXN: D19.1 J9.5 R54.1 | length 398
  BOTTOM w5.2: J9.5@2841.37,2585.45 2870.84,2585.45 2876.04,2580.25 2876.04,2540.04 2896.11,2519.97 2912.53,2519.97 2921.5,2511 2936.33,2511 2945.3,2519.97 2961.11,2519.97 2967.8,2513.28 2967.8,2449.25 2962.6,2444.05 ; R54.1@2945,2344.05 2961.68,2344.05 2968.2,2350.57 2968.2,2438.45 2962.6,2444.05 ; D19.1@2945,2444.05 2962.6,2444.05
USB30_RXP: D20.1 J9.6 R55.1 | length 390.2
  BOTTOM w5.2: J9.6@2920.11,2585.45 2890.64,2585.45 2885.44,2580.25 2885.44,2543.93 2900,2529.37 2965,2529.37 2977.2,2517.17 2977.2,2449.25 2982.4,2444.05 ; R55.1@3000,2344.05 2982.8,2344.05 2977.6,2349.25 2977.6,2439.25 2982.4,2444.05 ; D20.1@3000,2444.05 2982.4,2444.05
USB30_TXN: C63.1 D21.1 J9.8 | length 344.6
  BOTTOM w5.2: C63.1@3045,2344.05 3062.4,2344.05 3067.6,2349.25 3067.6,2438.85 3062.4,2444.05 ; D21.1@3045,2444.05 3062.4,2444.05 ; J9.8@3077.59,2585.45 3107.06,2585.45 3112.26,2580.25 3112.26,2531.66 3105,2524.4 3085.03,2524.4 3067.8,2507.17 3067.8,2449.25 3062.6,2444.05 3062.4,2444.05
USB30_TXP: C64.1 D22.1 J9.9 | length 345.2
  BOTTOM w5.2: C64.1@3100,2344.05 3082.2,2344.05 3077,2349.25 3077,2438.85 3082.2,2444.05 3082.4,2444.05 ; D22.1@3100,2444.05 3082.4,2444.05 ; J9.9@3156.33,2585.45 3126.86,2585.45 3121.66,2580.25 3121.66,2527.76 3108.89,2515 3088.92,2515 3077.2,2503.28 3077.2,2449.25 3082.4,2444.05
USB_HUB_3V3: C69.1 C70.1 C71.1 R60.2 R61.2 R62.2 R63.2 U8.1 U8.20 | length 908.5
  TOP w10: v1(3458.11,2349) R62.2@3458.11,2319.68 R61.2@3498.11,2319.68 3498.11,2365 3507.11,2374 3565.11,2374 3578.11,2361 R63.2@3578.11,2319.68 ; 3497.48,2146.37 v1(3497.48,2200.77)
  TOP w12: R60.2@3458.11,1944.68 C69.1@3498.11,1944.68 C70.1@3538.11,1944.68 3568.9,1975.47 U8.1@3568.9,2019.88 ; 3497.48,2146.37 3511.76,2132.09 U8.20@3535.43,2132.09
  TOP w15: R60.2@3458.11,1944.68 C71.1@3458.11,2132.09 3483.2,2132.09 3497.48,2146.37
  BOTTOM w10: v1(3458.11,2349) 3497.48,2309.63 v1(3497.48,2200.77)
USB_HUB_DM1: D24.1 J12.2 U8.11 | length 812.4
  TOP w5.2: U8.11@3700.79,2132.09 3726.55,2132.09 3731.69,2137.23 3776.2,2137.23 3792.11,2153.14 3792.11,2387.2 3810.51,2405.6 3931.89,2405.6 3947.4,2421.11 3947.4,2492.08 D24.1@3970,2514.68 3947.2,2537.48 3947.2,2662.08 J12.2@3981.97,2696.85
USB_HUB_DM2: D26.1 J13.2 U8.9 | length 2147.9
  TOP w5.2: U8.9@3700.79,2092.72 3726.55,2092.72 3731.69,2097.86 3825.6,2097.86 3843.51,2115.77 3843.51,2182.77 v1(3855.74,2195)
  BOTTOM w5.2: v1(3855.74,2195) 3843.51,2182.77 3843.51,2170.22 3831.89,2158.6 3799.11,2158.6 3785,2172.71 3785,2578 3812,2605 3863.7,2605 3864.1,2605.4 4398.4,2605.4 4410,2617 4410,2731 4439,2760 4519.6,2760 4530.6,2771 4530.6,2925.89 4547.41,2942.71 4599.29,2942.71 4615,2927 4615,2871.29 4638,2848.29 D26.1@4638,2844.69 4616.94,2823.63 4616.94,2729.52 J13.2@4649.61,2696.85
USB_HUB_DM3: D28.1 J14.3 U8.7 | length 1374.9
  TOP w5.2: U8.7@3700.79,2053.35 3726.55,2053.35 3731.69,2058.49 3803.31,2058.49 3813.71,2048.09 3813.71,1854.91 3829.62,1839 3858.88,1839 v1(3871.11,1826.77) ; v1(4547.11,1778.07) 4559.34,1790.3 4637.59,1790.3 4642.79,1785.1 ; D28.1@4642.79,1760 4642.79,1785.1 ; J14.3@4767.41,1754.17 4767.41,1783.64 4760.75,1790.3 4647.99,1790.3 4642.79,1785.1
  BOTTOM w5.2: v1(3871.11,1826.77) 3883.34,1839 4463.82,1839 4512.52,1790.3 4534.88,1790.3 v1(4547.11,1778.07)
USB_HUB_DM4: D38.1 J38.3 U8.5 | length 2066.9
  TOP w5.2: U8.5@3647.64,2019.88 3647.64,1994.12 3652.78,1988.98 3652.78,1977.73 3674.91,1955.6 3770.11,1955.6 3776.6,1949.11 3776.6,1696.71 3787.31,1686 3992.2,1686 4002.6,1675.6 4002.6,1321.32 4013.31,1310.62 4026.46,1310.62 v1(4038.31,1298.77) ; v1(4330.11,1185.37) 4341.74,1197 4482.29,1197 4499.4,1214.11 4499.4,1296.11 4511.09,1307.8 4637.59,1307.8 4642.79,1302.6 ; D38.1@4642.79,1275 4642.79,1302.6 ; J38.3@4767.41,1271.73 4767.41,1301.2 4760.81,1307.8 4647.99,1307.8 4642.79,1302.6
  ART03 w4.5: v1(4038.31,1298.77) 4050.49,1310.95 4135.5,1310.95 4144.5,1301.95 4144.5,1214.06 4161.01,1197.55 4317.93,1197.55 v1(4330.11,1185.37)
USB_HUB_DP1: D25.1 J12.3 U8.12 | length 808.6
  TOP w5.2: U8.12@3700.79,2151.77 3726.55,2151.77 3731.69,2146.63 3772.31,2146.63 3782.71,2157.03 3782.71,2391.09 3806.62,2415 3928,2415 3938,2425 3938,2491.68 D25.1@3915,2514.68 3937.8,2537.48 3937.8,2682.2 3923.15,2696.85 J12.3@3903.23,2696.85
USB_HUB_DP2: D27.1 J13.3 U8.10 | length 2146.6
  TOP w5.2: U8.10@3700.79,2112.4 3726.55,2112.4 3731.69,2107.26 3821.71,2107.26 3834.11,2119.66 3834.11,2188.89 3828,2195 v1(3821.88,2195)
  BOTTOM w5.2: v1(3821.88,2195) 3828.91,2195 3834.11,2189.8 3834.11,2174.11 3828,2168 3803,2168 3794.4,2176.6 3794.4,2277.22 3802,2284.82 3802,2298.02 3794.4,2305.62 3794.4,2318.82 3802,2326.42 3802,2339.62 3794.4,2347.22 3794.4,2360.42 3802,2368.02 3802,2381.22 3794.4,2388.82 3794.4,2402.02 3802,2409.62 3802,2422.82 3794.4,2430.42 3794.4,2443.62 3802,2451.22 3802,2464.42 3794.4,2472.02 3794.4,2485.22 3802,2492.82 3802,2506.02 3794.4,2513.62 3794.4,2526.82 3802,2534.42 3802,2547.62 3794.4,2555.22 3794.4,2574.11 3815.89,2595.6 3836.19,2595.6 3844.79,2587 3858.99,2587 3867.99,2596 4402.29,2596 4419.4,2613.11 4419.4,2727.11 4442.89,2750.6 4523.49,2750.6 4540,2767.11 4540,2922 4551.31,2933.31 4595.4,2933.31 4605.6,2923.11 4605.6,2867.29 D27.1@4583,2844.69 4583.22,2844.69 4607.54,2820.37 4607.54,2708.54 4595.85,2696.85 J13.3@4570.87,2696.85
USB_HUB_DP3: D29.1 J14.2 U8.8 | length 1372.8
  TOP w5.2: U8.8@3700.79,2073.03 3726.55,2073.03 3731.69,2067.89 3807.2,2067.89 3823.11,2051.98 3823.11,1858.8 3833.51,1848.4 3858.88,1848.4 v1(3871.11,1860.63) ; v1(4547.11,1811.93) 4559.34,1799.7 4637.59,1799.7 4642.79,1804.9 ; D29.1@4642.79,1830 4642.79,1804.9 ; J14.2@4767.41,1832.91 4767.41,1804.9 4762.21,1799.7 4647.99,1799.7 4642.79,1804.9
  BOTTOM w5.2: v1(3871.11,1860.63) 3883.34,1848.4 4467.71,1848.4 4516.41,1799.7 4534.88,1799.7 v1(4547.11,1811.93)
USB_HUB_DP4: D73.1 J38.2 U8.6 | length 2062.9
  TOP w5.2: U8.6@3667.32,2019.88 3667.32,1994.12 3662.18,1988.98 3662.18,1981.62 3678.8,1965 3774,1965 3786,1953 3786,1700.6 3791.2,1695.4 3996.09,1695.4 4012,1679.49 4012,1325.22 4017.2,1320.02 4025.69,1320.02 v1(4038.31,1332.63) ; v1(4330.11,1219.23) 4330.11,1211.6 4335.31,1206.4 4478.4,1206.4 4490,1218 4490,1300 4507.2,1317.2 4637.59,1317.2 4642.79,1322.4 ; D73.1@4642.79,1350 4642.79,1322.4 ; J38.2@4767.41,1350.47 4767.41,1322.4 4762.21,1317.2 4647.99,1317.2 4642.79,1322.4
  ART03 w4.5: v1(4038.31,1332.63) 4038.31,1325.69 4043.55,1320.45 4139.44,1320.45 4154,1305.88 4154,1218 4164.95,1207.05 4325.05,1207.05 4330.11,1212.11 v1(4330.11,1219.23)
VCC3V3_SD: C52.1 C53.1 D8.1 J3.8 J7.4 | length 1069
  TOP w15: v1(2346.08,2563) J7.4@2346.07,2618.11 ; v1(3262.31,858.23) 3266.24,854.29 J3.8@3310.59,854.29
  BOTTOM w15: v1(2346.08,2563) 2332.61,2576.47 D8.1@2332.61,2599.69 C53.1@2372.61,2599.69 2376.32,2599.69 2398.61,2621.98 2398.61,2683.69 C52.1@2372.61,2709.69 2348.24,2709.69 2333.24,2724.69 2333.24,2799.61 2357.63,2824 2583.37,2824 2612,2795.37 2612,2542.37 2624,2530.37 2680.46,2530.37 v1(2680.72,2530.63)
VCC3V3_WIFI: C121.1 C122.1 C123.1 C124.1 C125.1 C126.1 C127.1 R151.1 R164.1 R167.2 U16.9 U16.22 Y4.4 | length 620.7
  TOP w10: v1(3870.11,2280) R164.1@3903.43,2280 ; Y4.4@4077.83,1644.53 4078.11,1644.8 C123.1@4078.11,1700.32 4103.11,1725.32 4103.11,1786.25 v1(4080.11,1809.25) ; R151.1@4642.79,1925 v1(4673.11,1925)
  TOP w20: v1(3996.26,2405.63) v1(4035.63,2405.63) 4115.63,2405.63 4131.81,2421.81 C121.1@4131.81,2475.32 C122.1@4171.81,2475.32 U16.9@4171.81,2338.78
  other v1: 3970.67,1956.89 3970.67,1996.26
VCC5V0_SYS: C12.2 C13.1 C14.1 J3.1 J3.2 L3.2 R5.2 R12.1 | length 3399.8
  TOP w10: v1(3262.31,641.69) J3.2@3310.59,641.69 v1(3362.86,641.69)
  ART04 w10: v1(99.32,2868.69) 100.31,2868.69 128,2841 128,2722 153,2697 292,2697 336,2653 754,2653 774,2633 774,2487 797,2464 1835,2464 1858,2487 v1(1858,2631)
  BOTTOM w10: R12.1@99.32,2834.37 v1(99.32,2868.69) ; R5.2@1020,2000.32 C12.2@1060,2000.32 1060,1930 1089.96,1900.04 v1(1089.96,1838.11) ; v1(1858,2631) 2075,2631 2095,2611 2095,2525 2114,2506 2547,2506 2562.61,2521.61 v1(2562.61,2523.63)
  other v1: 3308.86,562.95 3362.86,562.95 3262.31,602.32 3362.86,602.32 1089.96,1720 1129.33,1720 1089.96,1759.37 1129.33,1759.37 1089.96,1798.74
VCC5V0_USB: C15.2 C16.1 C17.1 L4.2 R6.2 U7.5 U9.5 | length 353.4
  BOTTOM w10: v1(893.11,1877.48) 915.63,1900 963,1900 973,1910 973,2095.68 C15.2@948.68,2120 R6.2@948.68,2160
  other v1: 4391.22,1565 4312.48,1604.37 4351.85,1604.37 4391.22,1604.37 853.74,1759.37 893.11,1759.37 853.74,1798.74 853.74,1838.11 853.74,1877.48 2981,2977.37 2981,3021.74 3025.63,3021.74 3065,3021.74
VCC5V0_USB20_HUB: C75.1 C76.1 C78.1 C79.1 C80.1 C137.1 J12.1 J13.1 J14.4 J38.4 U9.1 | length 524.7
  TOP w10: C137.1@4642.79,1192.99 J38.4@4767.41,1192.99
  TOP w20: C80.1@4035,2514.68 4035,2651.45 J12.1@4080.4,2696.85
  BOTTOM w10: C75.1@4695,2844.69 v1(4724.32,2844.69)
  BOTTOM w20: C75.1@4695,2844.69 4695,2749.89 J13.1@4748.04,2696.85
  other v1: 4535.63,1232.36 4575,1232.36 4641.97,1586.69 4681.34,1586.69 4720.71,1586.69 4720.71,1626.06 4074.68,2514.68 4074.68,2554.05 4763.69,2844.69
VCC_LVDS: J17.1 J17.2 J17.3 J20.2 J20.4 J20.6 | length 1554.5
  TOP w20: J20.6@452.76,283.46 J20.4@531.5,283.46 J20.2@610.24,283.46 ; J17.3@1727.44,362.2 J17.1@1806.18,362.2
  BOTTOM w15: J20.2@610.24,283.46 610.24,281.76 660,232 1754.72,232 J17.2@1806.18,283.46 J17.1@1806.18,362.2
VCC_RTC: C117.1 D43.3 R130.1 R131.1 U15.8 | length 806
  TOP w10: v1(4673.11,2329.37) 4695.63,2329.37 4712.48,2312.52 v1(4712.48,2210)
  BOTTOM w10: R130.1@4378.11,2269.05 R131.1@4418.11,2269.05 4418.11,2319.37 4428.11,2329.37 v1(4673.11,2329.37) ; D43.3@4638.11,2180.37 4682.85,2180.37 v1(4712.48,2210)
  BOTTOM w12: U15.8@4479.72,2090.98 4512.72,2090.98 4520.11,2098.37 4520.11,2142.17 4531.99,2154.05 C117.1@4553.11,2154.05 4579.43,2180.37 D43.3@4638.11,2180.37
VCCA_1V8: J3.7 J26.1 J27.1 R171.1 | length 1382.5
  TOP w10: v1(3738,1727.37) 3738,1656 3755,1639 3939,1639 3968,1610 v1(3968,1410)
  TOP w15: v1(3262.31,818.86) J3.7@3310.59,818.86
  ART04 w20: 4013.63,810 J27.1@4042.28,810 ; 4042.28,781.34 J27.1@4042.28,810 ; 4042.28,838.66 J27.1@4042.28,810 ; 4070.94,810 J27.1@4042.28,810
  BOTTOM w10: v1(2486.22,449.37) v1@2486.37,449.37 ; R171.1@3334.68,1745 3342.08,1752.4 3539.6,1752.4 3564.63,1727.37 v1(3738,1727.37)
  BOTTOM w20: v1@2486.37,449.37 2500,463 2545,463 2563.75,481.75 v1(2563.75,673.22)
  other v1: 2486.22,410 2564,715.37 3262.31,779.49
VCCIO_ACODEC: J3.9 R18.2 | length 1035.5
  TOP w15: v1(3262.31,897.6) 3270.18,889.72 J3.9@3310.59,889.72
  BOTTOM w15: R18.2@2114.68,2889.37 2150.68,2925.37 2616,2925.37 2644,2897.37 2644,2578.37 2655,2567.37 2706,2567.37 2720.09,2553.28 v1(2720.09,2530.63)
VDD_3V3: C23.1 C24.1 C25.2 C68.1 C81.1 C85.1 C106.1 C107.1 C110.1 C111.1 C128.1 C136.1 C141.1 C157.1 C159.1 C160.1 D42.1 D43.2 J19.6 J21.4 L5.2 L13.1 L14.2 L15.1 L16.2 L17.1 R10.2 R13.1 R14.2 R15.2 R31.2 R60.1 R78.1 R80.1 R82.1 R167.1 R174.1 R175.1 R188.1 R189.1 R190.1 R191.1 R192.1 R260.1 U11.5 U12.5 U14.5 U17.24 U18.5 U19.5 U21.1 U21.5 U22.1 U22.5 U27.1 U27.3 | length 4063
  TOP w8: C128.1@705.32,1390 U21.1@705.32,1440.24 ; C136.1@705.32,1585 U22.1@705.32,1635.24 ; U21.5@725,1469.76 725,1492 v1(726,1493) ; U22.5@725,1664.76 725,1687 v1(726,1688)
  TOP w10: v1(70.06,2530.42) 106.42,2530.42 134.68,2558.68 C81.1@134.68,2559.37 ; U12.5@140.91,2628.94 140.91,2565.59 C81.1@134.68,2559.37 ; U11.5@305.91,2628.94 305.91,2565.59 C85.1@299.68,2559.37 276.88,2536.57 157.48,2536.57 C81.1@134.68,2559.37 ; U27.1@569.21,732.6 541.1,732.6 528,745.7 528,794.3 541.1,807.4 U27.3@569.21,807.4 ; C136.1@705.32,1585 705.32,1584.68 741.32,1548.68 v1(744.69,1548.68) ; v1(2929.29,256) J21.4@2929.29,331.1
  TOP w12: C107.1@744.68,1185 755.43,1174.25 U17.24@883.86,1174.25
  TOP w15: U27.1@569.21,732.6 609.71,732.6 v1(612,730.31) ; v1(1264.68,1077.32) C111.1@1264.68,1050 1264.68,1011.82 L13.1@1276.5,1000 ; R60.1@3458.11,1905.32 C68.1@3458.11,1839.68 3496.86,1839.68 v1(3497.43,1839.11) ; v1(3467.11,1154) L14.2@3467.11,1188.5 ; v1(3915.91,1207.37) 3967.13,1207.37 L16.2@3986,1188.5 ; v1(4845,296) R260.1@4845,330.32
  BOTTOM w10: R13.1@299.68,2834.37 v1(299.68,2868.69) ; R15.2@325.32,2120 325.32,2094 335.32,2084 601,2084 634.37,2050.63 v1(634.37,1879.48) ; R80.1@364.68,490 R82.1@364.68,530 364.68,552.68 374.68,562.68 v1(407.72,562.68) ; v1(634.37,1840.11) 648,1840.11 668,1860.11 668,2074 678,2084 730,2084 740,2094 R14.2@740,2150.32 C25.2@780,2150.32 ; v1(673.74,1800.74) 697,1824 697,2041 712,2056 924.68,2056 R10.2@948.68,2080 ; v1(1345,669.37) 1351.63,676 R191.1@1390.32,676 R192.1@1390.32,636 ; R31.2@2034.68,2969.37 v1(2065,2969.37) ; R190.1@2610,2139.06 R189.1@2650,2139.06 ; v1(2650,1994) R189.1@2650,2139.06 ; R174.1@2730,2139.06 R175.1@2690,2139.06 R189.1@2650,2139.06 ; v1(2929.29,256) v1(2929.29,216.63) 2930,215.92 D42.1@2930,184.68
  BOTTOM w15: v1@611.69,730 v1(612,730.31) ; v1(800,629) 840,589 R78.1@840,586.5 ; C110.1@1239.68,1080 1262,1080 v1(1264.68,1077.32) ; v1(3425,65) L17.1@3468.5,65 ; v1(4009,65) L15.1@4043.5,65 ; D43.2@4600.61,2100.37 4620,2080.98 v1(4620,2062) ; v1(4870.32,1350.32) C159.1@4870.32,1320 4870.32,1265 4880.32,1255 U19.5@4948.43,1255 ; U18.5@4948.43,830 4881,830 4870.32,840.68 C157.1@4870.32,880 4870.32,884.32 4893,907 4962.37,907 v1(4989.37,880)
  other v1: 4805.63,296 250,618 289.37,618 250,657.37 289.37,657.37 689.37,1345 728.74,1345 634.37,1761.37 673.74,1761.37 634.37,1800.74 3903.74,2210 3943.11,2210
VDD_5V: C2.2 C3.1 C4.1 C132.1 C143.1 C158.1 C161.1 L1.2 R1.2 R21.1 R32.1 R84.1 R132.1 R168.1 R169.1 R170.1 R172.1 R259.1 U13.5 U18.3 U19.3 U21.6 U22.6 | length 2209.9
  TOP w8: U21.6@705.32,1469.76 C132.1@705.32,1520 ; U22.6@705.32,1664.76 C143.1@705.32,1715
  TOP w10: v1(705.32,1548.68) C132.1@705.32,1520 679,1520 663,1536 663,1703 675,1715 C143.1@705.32,1715
  TOP w15: v1(4885,296) R259.1@4885,330.32
  BOTTOM w10: C2.2@325.32,2200 R1.2@325.32,2160 302.52,2137.2 302.52,2075.48 313,2065 428,2065 440,2053 v1(440,1843.11)
  BOTTOM w15: R170.1@364.68,2030 390.63,2030 400.63,2020 v1(400.63,1843.11) ; R169.1@364.68,2490 364.68,2292.32 380.23,2276.77 v1(413.82,2276.77) ; v1(971.85,1316) 971.85,1274.65 R21.1@1000,1246.5 ; R84.1@1060,586.5 1060,629 1077.1,646.1 v1(1169.53,646.1) ; U18.3@4751.57,780 4814.68,780 4824.68,790 C158.1@4824.68,880 v1(4824.68,906) ; U19.3@4751.57,1205 4814.68,1205 4824.68,1215 C161.1@4824.68,1320 4824.68,1362.68 4838,1376 4923.37,1376 v1(4940,1359.37) ; R132.1@4844.61,1620 v1(4880.74,1620)
  other v1: 4924.37,296 446.26,485 485.63,485 407.72,680.79 407.72,720.16 407.72,1133.52 407.72,1172.89 650,1298 650,1345 400.63,1764.37 440,1764.37 400.63,1803.74 440,1803.74
VDD_CAM0_5V: C108.1 C109.1 J24.1 J24.2 J24.3 R172.2
VDD_CAM1_5V: C129.1 C130.1 J28.1 J28.2 J28.3 R168.2
VDD_CAM2_5V: C134.1 C135.1 J29.1 J29.2 J29.3 R170.2
VDD_CAM3_5V: C131.1 C133.1 J30.1 J30.2 J30.3 R169.2
VDD_IO: D75.1 J22.6 R259.2 R260.2
VDD_LCD_3V3: C82.1 C139.1 C140.1 J18.4 J18.5 R176.1 R177.1 U14.1 | length 744.6
  TOP w10: U14.1@569.21,592.6 609.46,592.6 v1(611.43,590.63) ; v1(2639,324) 2668,324 2688,344 2688,414 2702.68,428.68 2898.37,428.68 v1(2919.37,449.68) 2940.38,428.67 3077.73,428.67 v1(3098.74,449.68)
  BOTTOM w10: C140.1@582.18,630 C139.1@582.18,590 610.8,590 v1(611.43,590.63) ; v1(2919.37,449.68) R177.1@2950,449.68 ; v1(3098.74,449.68) R176.1@3130,449.68
  other v1: 2599.63,324 611.43,630
VDD_LCD_5V: C83.1 C84.1 C86.1 J18.1 J18.2 J18.3 U13.1
  other v1: 697.63,207.37 737,207.37 2639,245.26 2639,284.63
VDD_LVDS: C100.1 C101.1 C102.1 C103.1 C142.1 C164.1 U10.35 U10.36 U10.38 U27.5 Y2.4 | length 978.7
  TOP w10: v1(715,983.47) Y2.4@757.28,983.47
  TOP w15: U27.5@470.79,732.6 v1(511.4,732.6) ; v1(651.37,769.68) 660,761.05 660,569 C100.1@689.68,539.32
  ART03 w10: v1(511.4,732.6) 493,751 493,830 504,841 504,928 524,948 679.53,948 v1(715,983.47)
  ART04 w15: v1(511.4,732.6) 538,706 640,706 651.37,717.37 v1(651.37,769.68)
VDDIO_LVDS: C91.1 C92.1 C93.1 C94.1 C112.1 C113.1 L13.2 R73.1 U10.10 U10.13 | length 677.3
  TOP w8: U10.10@1135.73,783.9 1158.9,783.9
  TOP w10: 1158.9,783.9 1186.1,783.9 1196.68,773.32 v1(1196.68,750) C93.1@1225.32,750 ; C113.1@1225.32,950 1248.32,973 1280.84,973 1295,958.84 v1(1295,875)
  TOP w15: v1(1157.63,870) 1197.63,910 C94.1@1225.32,910 C113.1@1225.32,950 1213.5,961.82 L13.2@1213.5,1000
  BOTTOM w10: v1(1157.63,870) 1157.68,869.95 C112.1@1157.68,830 C91.1@1157.68,790 1157.68,760.32 1168,750 v1(1196.68,750) C92.1@1225.32,750 ; R73.1@1264.68,875 v1(1295,875)
WL_HOST_WAKE: J3.49 R166.1 | length 1039.5
  TOP w6.8: v1(3188.85,2149.85) 3188.85,2293.45 3202.45,2307.05 J3.49@3310.59,2307.05 ; v1(3870.11,2240) R166.1@3903.43,2240
  ART03 w6.3: v1(3188.85,2149.85) 3196,2157 3632,2157 3690,2215 3774,2215 3819,2260 3850.11,2260 v1(3870.11,2240)
WL_REG_ON: J3.48 R165.1 | length 1104.1
  TOP w6.8: v1(3188.85,2110.48) 3210,2131.63 3210,2258.01 3223.6,2271.61 J3.48@3310.59,2271.61 ; v1(3831.71,2240) 3831.71,2308.6 3843.11,2320 R165.1@3903.43,2320
  ART03 w6.3: v1(3188.85,2110.48) 3219.37,2141 3646,2141 3704,2199 3790.71,2199 v1(3831.71,2240)
pads on no net: J1. J3.5 J3.85 J3.86 J5. J5.7 J5.8 J7. J18.14 J24.13 J24.14 J24.16 J24.17 J24.18 J24.19 J24.20 J24.21 J28.13 J28.14 J28.16 J28.17 J28.18 J28.19 J28.20 J28.21 J29.13 J29.14 J29.16 J29.17 J29.18 J29.19 J29.20 J29.21 J30.13 J30.14 J30.16 J30.17 J30.18 J30.19 J30.20 J30.21 SW1.2 U8.2 U8.19 U8.21 U8.22 U8.23 U8.24 U10.3 U10.4 U10.6 U16.4 U16.5 U16.8 U16.10 U16.11 U16.21 U16.23 U16.29 U16.30 U16.32 U16.35 U16.37 U16.38 U16.39 U16.40 U16.45 U16.46 U16.47 U17.1 U17.14 U17.15 U17.16 U17.17 U17.18 U17.19 U17.20 Y2.1 Y4.1

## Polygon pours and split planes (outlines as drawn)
VDD_CAM3_5V on BOTTOM "BOTTOM-VDD_CAM3_5V" (solid, pour order 33): 337,2478 337,2636 328,2645 232,2645 232,2593 308,2593 314,2587 314,2478 337,2478
VCC5V0_USB20_HUB on BOTTOM "BOTTOM-VCC5V0_USB20_HUB" (solid, pour order 5): 82 vertices, not listed, extent 4683,2831.37 4776,2856.37
N16783279 on BOTTOM "BOTTOM-N16783279" (solid, pour order 60): 533,1144 533,1202 1063,1202 1071,1194 1071,1168 971,1168 958,1155 958,1130 957,1129 548,1129 544,1133 539,1138 533,1144
VDD_CAM2_5V on BOTTOM "BOTTOM-VDD_CAM2_5V" (solid, pour order 31): 232,1961 305,1961 314,1970 314,2042 337,2042 337,1919 327,1909 232,1909 232,1961
VDD_LCD_3V3 on BOTTOM "BOTTOM-VDD_LCD_3V3" (solid, pour order 18): 82 vertices, not listed, extent 570,578 626,643
GND on BOTTOM "BOTTOM-GND" (solid, pour order 79): 90 vertices, not listed, extent 20,20 5078.42,3090.24
VDD_CAM0_5V on BOTTOM "BOTTOM-VDD_CAM0_5V" (solid, pour order 30): 284,540 284,551 291,558 329,558 337,566 337,717 314,717 314,596 309,591 233,591 233,540 284,540
USB30_OTG_VBUS on BOTTOM "BOTTOM-USB30_OTG_VBUS" (solid, pour order 37): 3157,2921.37 3010,2921.37 3001,2912.37 3001,2856.37 3024,2856.37 3147,2856.37 3157,2866.37 3157,2898.37 3157,2921.37
VCC5V0_USB on BOTTOM "BOTTOM-VCC5V0_USB" (solid, pour order 24): 3024,2955.37 2979,2955.37 2971,2963.37 2971,3025.37 2979,3033.37 3070,3033.37 3076,3027.37 3076,3010.37 3068,3002.37 3034,3002.37 3024,2992.37 3024,2955.37
12V on BOTTOM "BOTTOM-12V" (solid, pour order 42): 19 vertices, not listed, extent 716,2227 829,2380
